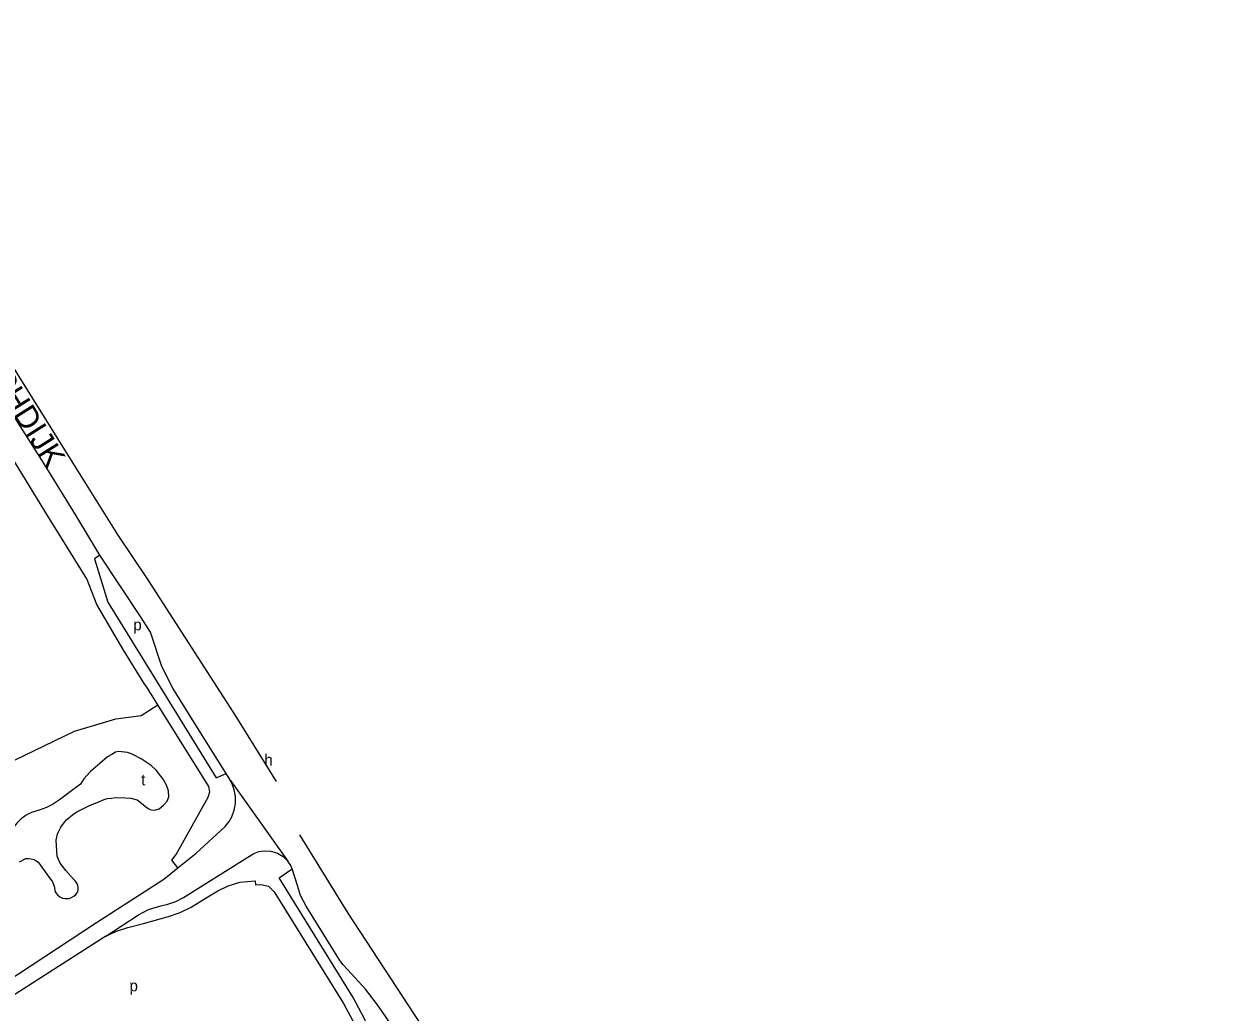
# Model space of a CAD drawing. Extents: x 158142 to 159655, y 385262 to 387204.
# Drawn here: x 159056.3 to 159478, y 386634 to 386982.8 of the extents above; entities that cross this region are included whole.
import ezdxf

# ---------------------------------------------------------------- set-up
doc = ezdxf.new("R2010")
doc.units = 0
for name, color, linetype in [('BLT_Basislijn', 7, 'Continuous'), ('BLT_Centroide', 7, 'Continuous'), ('BLT_Straatnaam', 7, 'Continuous'), ('BLT_Vlakafsluiter', 7, 'Continuous')]:
    doc.layers.add(name, color=color, linetype=linetype)

msp = doc.modelspace()

# ---------------------------------------------------------------- linework, layer by layer
at = {"layer": 'BLT_Basislijn'}
for points in [[(159103.65, 386742.39), (159099.94, 386748.36), (159098.83, 386750), (159091.4, 386761.9), (159082.06, 386777.82), (159078.59, 386786.94), (159064.74, 386809.3), (158958.42, 386982.75)], [(159083.22, 386795.27), (159074.66, 386809.4), (159063.45, 386827.49), (159040.75, 386863.13), (159025.87, 386887.16), (158965.29, 386982.75)], [(159089.59, 386802.28), (159073.79, 386827.75), (159023.04, 386908.93), (158995.81, 386951.04), (158976.07, 386982.75)], [(159145.52, 386715.41), (159131.33, 386738.34), (159100, 386786.87), (159089.59, 386802.28)], [(159083.22, 386795.27), (159081.29, 386794.01), (159085.93, 386778.65), (159124.29, 386716.67), (159127.74, 386718.23)], [(159127.74, 386718.23), (159117.69, 386734.33), (159108.97, 386748.3), (159105.09, 386755.97), (159101.03, 386768.04), (159097.49, 386773.62), (159083.22, 386795.27)], [(159032.59, 386711.15), (159053, 386722.91), (159074.25, 386733.11), (159088.84, 386737.48), (159097.73, 386738.7), (159103.65, 386742.39)], [(159110.71, 386684.88), (159108.59, 386687.57), (159110.12, 386689.58), (159121.42, 386709.83), (159122.03, 386711.68), (159121.59, 386713.58), (159103.65, 386742.39)], [(159106.54, 386714.32), (159105.47, 386716.2), (159104.74, 386717.28), (159103.17, 386719.22), (159101.27, 386721.03), (159097.81, 386723.32), (159094.59, 386725.03), (159092.93, 386725.56), (159089.81, 386725.91), (159088.69, 386725.66), (159087.37, 386724.93), (159085.91, 386724.05), (159083.13, 386721.66), (159079.87, 386718.95), (159078.45, 386717.36), (159077.55, 386716.28), (159076.35, 386714.41), (159073.66, 386712.38), (159068.93, 386708.89), (159066.46, 386707.26), (159064.34, 386706.24), (159061.7, 386705.29), (159059, 386704.48)], [(159129.29, 386715.75), (159127.74, 386718.23)], [(159054.78, 386687.06), (159057.09, 386688.2), (159058.02, 386688.22), (159058.85, 386688.11), (159059.85, 386687.83), (159060.53, 386687.54), (159061.36, 386686.9), (159062.11, 386685.95), (159065.61, 386681.04), (159066.31, 386680.13), (159067.08, 386678.38), (159067.37, 386676.48), (159067.67, 386676.02), (159068.25, 386675.32), (159069.02, 386674.67), (159070.02, 386674.14), (159070.95, 386674.02), (159072.35, 386674.1), (159073.16, 386674.37), (159073.96, 386674.88), (159074.67, 386675.51), (159075.1, 386676.1), (159075.46, 386677.01), (159075.46, 386677.88), (159075.36, 386678.64), (159074.99, 386679.49), (159074.58, 386680.16), (159073.85, 386680.9), (159071.2, 386684), (159069.97, 386685.49), (159069.13, 386686.59), (159068.57, 386687.8), (159068.11, 386689.04), (159067.92, 386690.75), (159067.77, 386694.6), (159067.92, 386695.76), (159068.09, 386696.44), (159068.45, 386697.35), (159069.4, 386699.24), (159070.65, 386700.97), (159071.55, 386701.93), (159073.5, 386703.64), (159075.03, 386704.6), (159076.72, 386705.53), (159079.33, 386706.77), (159082.46, 386708.1), (159084.67, 386709.04), (159085.77, 386709.31), (159087.24, 386709.52), (159088.76, 386709.68), (159092.06, 386709.58), (159094.14, 386709.48), (159096.29, 386708.89), (159098.52, 386707.27), (159099.4, 386706.41), (159100.17, 386705.79), (159100.97, 386705.43), (159102.01, 386705.2), (159102.99, 386705.39), (159104.06, 386705.74), (159105.7, 386706.99), (159106.98, 386708.43), (159107.49, 386709.98), (159107.42, 386711.95), (159107.23, 386712.75), (159106.54, 386714.32)], [(159110.71, 386684.88), (159117.16, 386690.11), (159127.37, 386699.43), (159128.81, 386701.19), (159129.72, 386702.87), (159130.56, 386705.24), (159131.01, 386707.55), (159131.04, 386710.05), (159130.63, 386712.45), (159130.04, 386714.15), (159129.29, 386715.75)], [(159059, 386704.48), (159057.14, 386703.47), (159055.39, 386702.19), (159053.81, 386700.67), (159052.44, 386698.94), (159051.33, 386697.04), (159050.49, 386695.05), (159049.93, 386693), (159049.93, 386685.6)], [(159205.26, 386616.42), (159170.82, 386668.91), (159153.76, 386696.49)], [(159085.3, 386660.77), (159096.78, 386668.36), (159100.39, 386670.21), (159104.75, 386671.43), (159107.18, 386672.07), (159110, 386673.06), (159112.65, 386674.45), (159134.43, 386688.08), (159137.54, 386689.97), (159139.35, 386690.67), (159141.21, 386690.94), (159143.49, 386690.83), (159145.85, 386690.1), (159147.9, 386688.89), (159149.6, 386687.23)], [(159151.12, 386684.55), (159150.63, 386685.69), (159149.6, 386687.23)], [(159049.58, 386644.33), (159081.97, 386665.65), (159105.75, 386680.86), (159110.71, 386684.88)], [(159478.02, 386149.53), (159467.1, 386166.67), (159451.19, 386191.65), (159448.58, 386196.2), (159403.98, 386267.32), (159376.84, 386309.95), (159320.35, 386401.06), (159194.99, 386601.74), (159190.31, 386604.18), (159180.82, 386620.38), (159176.63, 386631.64), (159172.66, 386639.08), (159146.46, 386681.4), (159151.12, 386684.55)], [(159170.69, 386648.92), (159168.91, 386650.83), (159167.74, 386652.44), (159165.4, 386656.24), (159155.96, 386671.42), (159154.05, 386675.09), (159152.99, 386678.66), (159151.12, 386684.55)], [(159085.3, 386660.77), (159089.06, 386662.5), (159093, 386663.81), (159098.61, 386665.26), (159107.4, 386667.76), (159111.54, 386669.09), (159115.44, 386670.99), (159121.25, 386674.65), (159124.79, 386676.76), (159128.48, 386678.59), (159132.54, 386679.78), (159138.02, 386680.36), (159138.09, 386678.86), (159140.02, 386678.97), (159142.72, 386678.38), (159144.72, 386676.48), (159169.22, 386637.05), (159172.52, 386630.87), (159175.32, 386623.61), (159177.48, 386618.34)], [(159085.3, 386660.77), (159053.17, 386640.17), (159044.04, 386630.1), (159040.22, 386623.44), (159037.96, 386617.94), (159037.14, 386612.74), (159038.41, 386607.15), (159041.39, 386602.67), (159045.98, 386599.46), (159059.02, 386591.14), (159060.49, 386588.42)], [(159197.96, 386612.2), (159192.8, 386619.56), (159181.61, 386636.06), (159176.92, 386642.07), (159170.69, 386648.92)]]:
    msp.add_lwpolyline(points, dxfattribs=at)
at = {"layer": 'BLT_Vlakafsluiter'}
msp.add_line((159129.29, 386715.75), (159149.6, 386687.23), dxfattribs=at)

# ---------------------------------------------------------------- texts
at = {"layer": 'BLT_Centroide'}
for s, p in [('p', (159094.97, 386768.71)), ('h', (159141.24, 386720.98)), ('t', (159097.76, 386714)), ('p', (159093.63, 386641.31))]:
    msp.add_text(s, height=4, dxfattribs=at).set_placement(p)
at = {"layer": 'BLT_Straatnaam'}
msp.add_text('BOSCHDIJK', height=8, rotation=302.2071, dxfattribs=at).set_placement((159032.06, 386877.14))

doc.saveas('drawing.dxf')
